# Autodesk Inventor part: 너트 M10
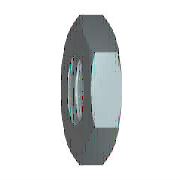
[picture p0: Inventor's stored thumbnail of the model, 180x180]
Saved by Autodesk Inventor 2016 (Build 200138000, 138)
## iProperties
IsCustomPart: 1
Created: 2012-02
Part Number: 너트 M10
Material: 강철, 연강
Description: 6각 가는 너트 - 이중 모따기
Document SubType Name: Modeling
Standard: JIS B 1181
Designer: mduedu
Standards Organization: JIS
Language: ko-KR
Size Designation: A/B M10
Categories: <MemberInstance><Categories><Category DisplayName="조임쇠" InternalName="e4da775c-781d-43d5-af7c-5136215cf5a6" Mnemonic="FSTN"><Category DisplayName="너트" InternalN
Density: 1 g/cm^3
Appearance: 주황색
Author: mduedu
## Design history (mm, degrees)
sketch "스케치1"
  geometry: L1 (-9.238, 0)-(-4.619, 8); L2 (-4.619, 8)-(4.619, 8); L3 (4.619, 8)-(9.238, 0); L4 (9.238, 0)-(4.619, -8); L5 (4.619, -8)-(-4.619, -8); L6 (-4.619, -8)-(-9.238, 0); 2 further points
  constraints: 12 end point, 1 coincident, 1 horizontal, 11 other
  dimensions: "d0" = 18.47521 distance of L3.end L1.start (= 1.1547 x SW)
extrude "본체" new body sketch "스케치1" distance "d1" = 5 (= KOH); taper "d2" = 0 deg
sketch "스케치2"
  geometry: L1 (0, 4.619)-(0, 9.238) reference; L2 (0, 9.238)-(5, 9.238) reference; L3 (5, 4.619)-(5, 9.238) reference; L4 (-1, 0)-(6, 0) reference; L5 (0.715, 9.238)-(0, 8); L6 (4.285, 9.238)-(5, 8)
  constraints: 4 end point, 4 point on line
  dimensions: "d3" = 30 deg angle of L1 L5 (= ANG1); "d4" = 30 deg angle of L3 L6 (= ANG2); "d5" = 16 diameter of L5.end L4 (= SW0); "d6" = 16 diameter of L6.end L4 (= SW01)
revolve "모따기1" sketch "스케치2" stored, may be unused: angle "d7" = 90 deg
sketch "스케치3"
  geometry: A1 r 8 centre (0, 0) between (-4, -6.928) and (4, -6.928) reference; 1 further point
  constraints: 1 coincident
hole "스레드" sketch "스케치3" at (0, 0) diameter "d25" = 8.376; stored, may be unused: countersink angle "d29" = 82 deg, drill point angle "d31" = 118 deg; dims "d26" = 6, "d27" = 4, "d28" = 2, "d30" = 8
workaxis "Work Axis1"
workplane "Work Plane1"
body "Solid1"
chamfer "모따기2" distance "d8" = 0.8119 (= -0.5 x GD1 + 0.5 x NND); stored, may be unused: angle "d9" = 30 deg, second distance "d40" = 0.8119 (= -0.5 x GD1 + 0.5 x NND)
chamfer "모따기3" distance "d10" = 0.8119 (= -0.5 x GD1 + 0.5 x NND); stored, may be unused: angle "d11" = 30 deg, second distance "d41" = 0.8119 (= -0.5 x GD1 + 0.5 x NND)
other parameters: "ANG1" = 30 deg [user parameter; used in 1 equation term], "ANG2" = 30 deg [user parameter; used in 1 equation term], "KOH" = 5 [user parameter; used in 1 equation term], "SW" = 16 [user parameter; used in 4 equation terms], "SW0" = 16 (= SW) [user parameter; used in 1 equation term], "SW01" = 16 (= SW) [user parameter; used in 1 equation term], "GD1" = 8.3762 (computed from THREADDIA, PTC, TOA) [user parameter; used in 4 equation terms], "d13" = 0, "d14" = 0, "d39" = 0, "d42" = 0, "GUL" = 0.8119 (= 0.541266 x PTC) [user parameter], "TPU" = 6.66667 (computed from PTC) [user parameter], "TOA" = 30 deg [user parameter; used in 1 equation term], "PTC" = 1.5 [user parameter; used in 4 equation terms], "E0" = 18.48 (= 1.155 x SW) [user parameter], "GAL" = 0.8119 (= 0.541266 x PTC) [user parameter]
